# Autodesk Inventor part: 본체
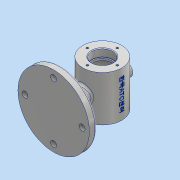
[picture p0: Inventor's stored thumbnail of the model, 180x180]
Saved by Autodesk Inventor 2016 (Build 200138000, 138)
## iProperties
Created: 2018-12
Part Number: 본체
Material: 알루미늄 6061
Document SubType Name: Modeling
Designer: 3sil_cad018
Density: 2.7 g/cm^3
Appearance: 알루미늄 - 평지
Mass: 683.279 g
Surface Area: 559.795 cm^2
Volume: 253.066 cm^3
Author: 3sil_cad018
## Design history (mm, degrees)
sketch "스케치1"
  geometry: C1 r 30 at (0, 0); 1 further point
  constraints: 1 centre point, 1 coincident
  dimensions: "d0" = 60 diameter of C1
extrude "돌출1" new body sketch "스케치1" distance "d1" = 70; taper "d2" = 0 deg
node "작업 평면2"
sketch "스케치5"
  geometry: L1 (30, 70)-(-30, 70) reference; L2 (-30, 0)-(30, 0) reference; L3 (30, 0)-(30, 70) reference; L4 (-30, 0)-(-30, 70) reference; C1 r 55 at (0, 35); 3 further points
  constraints: 2 midpoint, 1 centre point, 1 horizontal alignment, 1 vertical alignment
  dimensions: "d8" = 110 diameter of C1
extrude "돌출3" join sketch "스케치5" distance "d9" = 11; taper "d10" = 0 deg
sketch "스케치6"
  geometry: L1 (-64, -20)-(-64, 90) reference; L2 (-64, 35)-(-14, 35); L3 (-14, 35)-(-14, 47); L4 (-14, 47)-(-52.478, 47); L5 (-52.478, 47)-(-64, 90); L6 (-64, 90)-(-64, 35); L7 (-75, 90)-(-64, 90) reference; 1 further point
  constraints: 10 end point, 2 perpendicular, 1 collinear, 1 horizontal, 1 midpoint
  dimensions: "d11" = 24 diameter of L4 L2; "d12" = 75 deg angle of L7 L5; "d13" = 50 distance of L2.start L2.end
revolve "회전1" sketch "스케치6" stored, may be unused: angle "d14" = 90 deg
fillet "모깎기1" dims "d15" = 3
sketch "스케치7"
  geometry: L1 (30, 70)-(-30, 70) reference; L2 (16, 70)-(16, 58); L3 (16, 58)-(14, 58); L4 (14, 58)-(14, 55); L5 (14, 55)-(25, 55); L6 (25, 55)-(25, 15); L7 (25, 15)-(14, 15); L8 (14, 15)-(14, 12); L9 (14, 12)-(16, 12); L10 (16, 12)-(16, 0); L11 (16, 0)-(0, 0); L12 (-30, 0)-(30, 0) reference; L13 (0, 0)-(0, 70); L14 (0, 70)-(16, 70); 3 further points
  constraints: 24 end point, 7 perpendicular, 5 point on line, 4 midpoint, 1 collinear, 1 horizontal, 1 vertical, 1 vertical alignment
  dimensions: "d16" = 12 distance of L2.start L2.end; "d17" = 40 distance of L5.end L6.end; "d18" = 3 distance of L3.end L4.end; "d19" = 12 distance of L9.end L10.end; "d20" = 32 diameter of L2 L13; "d21" = 28 diameter of L4 L13; "d22" = 50 diameter of L6 L13
revolve "회전2" sketch "스케치7" stored, may be unused: angle "d23" = 90 deg
fillet "모깎기2" dims "d24" = 3
node "작업 평면3"
sketch "스케치8"
  geometry: L1 (30, 35)-(-30, 35) reference; L2 (-30, -35)-(30, -35) reference; L3 (-30, -35)-(-30, 35) reference; C1 r 10 at (0, 0); 4 further points
  constraints: 2 midpoint, 1 centre point, 1 horizontal alignment, 1 vertical alignment, 1 other
  dimensions: "d26" = 20 diameter of C1
extrude "돌출4" join sketch "스케치8" stored distance "d27" = 10; taper "d28" = 0 deg
sketch "스케치9"
  geometry: C1 r 5 at (0, 0); C2 r 10 at (0, 0) reference; 1 further point
  constraints: 1 centre point, 1 coincident
  dimensions: "d29" = 10 diameter of C1
extrude "돌출5" cut sketch "스케치9" distance "d30" = 20; taper "d31" = 0 deg
sketch "스케치10"
  geometry: C1 r 55 at (0, 0) reference; 2 further points
  constraints: 1 vertical alignment
  dimensions: "d32" = 44 distance of point (0, 44) C1.centre
hole "구멍1" sketch "스케치10" at (0, 44) diameter "d33" = 9; stored, may be unused: countersink angle "d37" = 90 deg, drill point angle "d39" = 118 deg; dims "d34" = 6, "d35" = 4, "d36" = 2, "d38" = 8
node "작업 평면4"
sketch "스케치11"
  geometry: C1 r 7 at (0, 43.54); 4 further points
  constraints: 2 vertical alignment, 1 centre point, 1 coincident, 1 horizontal alignment, 2 other
  dimensions: "d41" = 14 diameter of C1
extrude "돌출6" cut sketch "스케치11" distance "d42" = 20; taper "d43" = 0 deg
sketch "스케치12"
  geometry: C1 r 25 at (0, 0) reference; C2 r 30 at (0, 0) reference; 2 further points
  constraints: 1 vertical alignment
  dimensions: "d47" = 23 distance of point (0, 0) point (0, 23)
hole "구멍2" sketch "스케치12" at (0, 23) diameter "d48" = 3.242; stored, may be unused: countersink angle "d52" = 90 deg, drill point angle "d54" = 118 deg; dims "d49" = 8, "d50" = 4, "d51" = 2, "d53" = 10
node "작업 평면5"
node "작업 평면6"
node "작업 평면8"
sketch "스케치16"
  geometry: L1 (30, 0)-(30, 70) reference; L2 (30, 70)-(-30, 70) reference; 2 further points
  constraints: 1 other
  dimensions: "d62" = 30 distance from line of point (0, 35) L1; "d63" = 35 distance from line of point (0, 35) L2
feature "엠보싱1" sketch "스케치16" dims "d64" = 0.5, "d65" = 0
fillet "모깎기3" dims "d66" = 3
fillet "모깎기4" dims "d67" = 0.3
chamfer "모따기1" distance "d68" = 1; stored, may be unused: second distance "d69" = 2, angle "d70" = 45 deg
chamfer "모따기2" distance "d71" = 1; stored, may be unused: second distance "d72" = 2, angle "d73" = 45 deg
fillet "모깎기5" dims "d74" = 3
node "솔리드1"
pattern_circular "원형 패턴1" dims angle "d45" = 360 deg
pattern_circular "원형 패턴2" dims angle "d56" = 360 deg
mirror "대칭1"
node "투영된 루프2"
node "투영된 루프3"
node "투영된 루프4"
node "투영된 루프5"
other parameters: "d7" = -75, "d25" = -112, "d58" = -35, "d61" = 62.25
